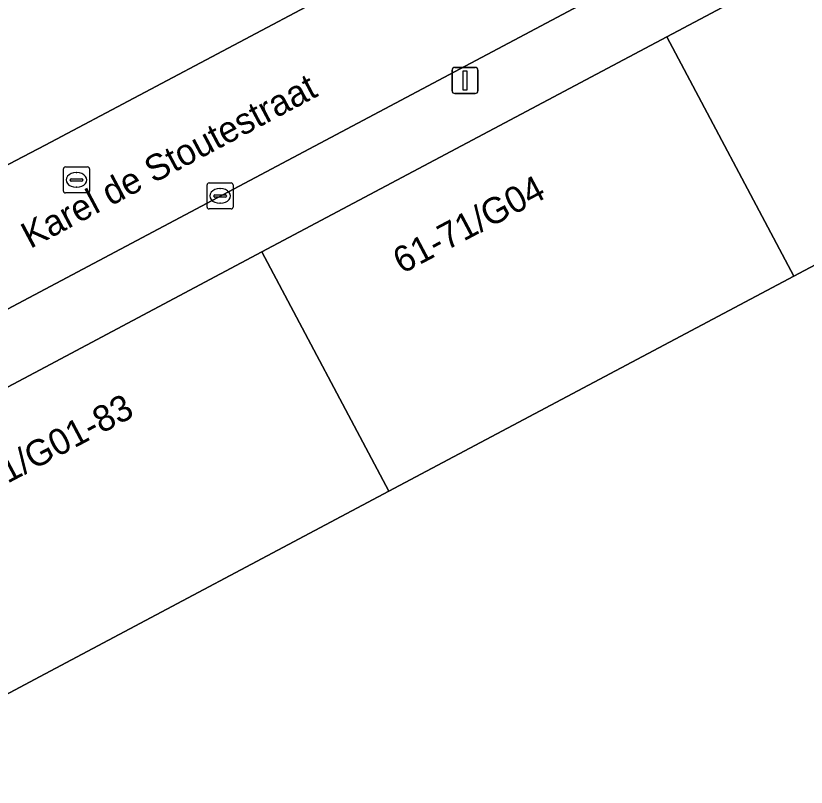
# Model space of a CAD drawing. Extents: x 159674 to 160531, y 382172 to 382904.
# Drawn here: x 159998.88 to 160029.22, y 382302.8 to 382332.4 of the extents above; entities that cross this region are included whole.
import ezdxf

# ---------------------------------------------------------------- set-up
doc = ezdxf.new("R2010")
doc.units = 0
for name, color, linetype in [('IMGEO_Groenvoorziening', 7, 'Continuous'), ('IMGEO_Kolk', 7, 'Continuous'), ('IMGEO_Lichtmast', 7, 'Continuous'), ('IMGEO_Openbare_ruimte_label', 7, 'Continuous'), ('IMGEO_Pand', 7, 'Continuous'), ('IMGEO_Pand_nummerreeks', 7, 'Continuous'), ('IMGEO_Parkeervlak_open', 7, 'Continuous'), ('IMGEO_Rijbaan_lokaal_open', 7, 'Continuous'), ('IMGEO_Rioolput', 7, 'Continuous'), ('IMGEO_Voetpad_open', 7, 'Continuous')]:
    doc.layers.add(name, color=color, linetype=linetype)

msp = doc.modelspace()

# ---------------------------------------------------------------- linework, layer by layer
at = {"layer": 'IMGEO_Groenvoorziening'}
for points in [[(160069.876, 382317.999), (160071.602, 382320.568), (160072.224, 382321.861), (160072.647, 382323.232), (160045.381, 382343.017), (160039.422, 382339.84), (160044.297, 382330.659), (160028.751, 382322.408), (160013.206, 382314.156), (160000, 382307.147), (159997.66, 382305.905), (159982.114, 382297.653), (159977.237, 382306.837), (159966.979, 382301.422), (160000, 382277.384), (160003.473, 382274.856), (160014.527, 382280.815), (160013.011, 382283.689), (160015.445, 382285.033)], [(159998.879, 382326.843), (160000, 382327.438), (160010.873, 382333.212), (160009.916, 382335.059), (160011.76, 382336.052), (160012.767, 382334.217), (160024.689, 382340.548)]]:
    msp.add_lwpolyline(points, dxfattribs=at)
at = {"layer": 'IMGEO_Kolk'}
for p, q in [((160006.222, 382325.062), (160006.222, 382325.914)), ((160006.297, 382325.988), (160007.149, 382325.988)), ((160007.223, 382325.914), (160007.223, 382325.062)), ((160006.524, 382325.531), (160006.922, 382325.531)), ((160006.71, 382325.768), (160006.735, 382325.768)), ((160006.481, 382325.482), (160006.481, 382325.494)), ((160006.919, 382325.445), (160006.521, 382325.445)), ((160006.965, 382325.494), (160006.965, 382325.482)), ((160007.149, 382324.988), (160006.297, 382324.988)), ((160006.733, 382325.208), (160006.708, 382325.208))]:
    msp.add_line(p, q, dxfattribs=at)
for points in [[(160006.222, 382325.062), (160006.222, 382325.914)], [(160006.297, 382325.988), (160007.149, 382325.988)], [(160007.223, 382325.914), (160007.223, 382325.062)], [(160007.149, 382324.988), (160006.297, 382324.988)]]:
    msp.add_lwpolyline(points, dxfattribs=at)
for centre, radius, start, end in [((160006.299, 382325.912), 0.0765, 91.552, 178.448), ((160006.299, 382325.912), 0.0765, 91.552, 178.448), ((160007.147, 382325.912), 0.0765, 1.552, 88.448), ((160007.147, 382325.912), 0.0765, 1.552, 88.448), ((160006.521, 382325.491), 0.0403, 85.8775, 175.7526), ((160006.926, 382325.493), 0.0386, 1.7309, 96.639), ((160006.518, 382325.481), 0.0366, 178.938, 274.7102), ((160006.922, 382325.488), 0.043, 264.8664, 352.4533), ((160006.299, 382325.064), 0.0765, 181.552, 268.448), ((160006.299, 382325.064), 0.0765, 181.552, 268.448), ((160007.147, 382325.064), 0.0765, 271.552, 358.448), ((160007.147, 382325.064), 0.0765, 271.552, 358.448)]:
    msp.add_arc(centre, radius, start, end, dxfattribs=at)
for centre, major_axis, ratio, start_param, end_param in [((160006.709, 382325.488), (-0.387, 0.002), 0.722429, 4.712389, 7.853982), ((160006.734, 382325.488), (-0.39, 0.002), 0.717154, 1.570796, 4.712389)]:
    msp.add_ellipse(centre, major_axis=major_axis, ratio=ratio, start_param=start_param, end_param=end_param, dxfattribs=at)
at = {"layer": 'IMGEO_Lichtmast'}
for p, q in [((160015.729, 382330.42), (160016.519, 382330.42)), ((160016.519, 382330.42), (160015.729, 382330.42)), ((160015.629, 382329.52), (160015.629, 382330.32)), ((160015.629, 382330.32), (160015.629, 382329.52)), ((160016.619, 382330.32), (160016.619, 382329.52)), ((160016.619, 382329.52), (160016.619, 382330.32)), ((160016.519, 382329.42), (160015.729, 382329.42)), ((160015.729, 382329.42), (160016.519, 382329.42))]:
    msp.add_line(p, q, dxfattribs=at)
msp.add_lwpolyline([(160016.049, 382330.295), (160016.199, 382330.295), (160016.199, 382329.545), (160016.049, 382329.545), (160016.049, 382330.295)], dxfattribs=at)
for centre, start, end in [((160015.729, 382330.32), 90, 180), ((160015.729, 382330.32), 90, 180), ((160016.519, 382330.32), 0, 90), ((160016.519, 382330.32), 360, 90), ((160015.729, 382329.52), 180, 270), ((160015.729, 382329.52), 180, 270), ((160016.519, 382329.52), 270, 0), ((160016.519, 382329.52), 270, 0)]:
    msp.add_arc(centre, 0.1, start, end, dxfattribs=at)
at = {"layer": 'IMGEO_Pand'}
for points in [[(160028.751, 382322.408), (160044.297, 382330.659), (160039.422, 382339.84), (160023.876, 382331.589)], [(160008.329, 382323.339), (160013.206, 382314.156), (160028.751, 382322.408), (160023.876, 382331.589)], [(159992.783, 382315.088), (159997.66, 382305.905), (160000, 382307.147), (160013.206, 382314.156), (160008.329, 382323.339), (160000, 382318.918)]]:
    msp.add_lwpolyline(points, close=True, dxfattribs=at)
at = {"layer": 'IMGEO_Parkeervlak_open'}
msp.add_lwpolyline([(159979.237, 382316.488), (159998.879, 382326.843)], dxfattribs=at)
at = {"layer": 'IMGEO_Rijbaan_lokaal_open'}
for points in [[(160024.689, 382340.548), (160012.767, 382334.217), (160010.873, 382333.212), (160000, 382327.438), (159998.879, 382326.843), (159979.237, 382316.488)], [(159977.738, 382314.014), (159977.115, 382313.657), (159975.28, 382312.603), (159974.461, 382312.133), (159975.985, 382309.171), (160000, 382321.916), (160022.355, 382333.786)]]:
    msp.add_lwpolyline(points, dxfattribs=at)
at = {"layer": 'IMGEO_Rioolput'}
for p, q in [((160000.708, 382325.676), (160000.708, 382326.528)), ((160000.783, 382326.602), (160001.635, 382326.602)), ((160001.709, 382326.528), (160001.709, 382325.676)), ((160001.01, 382326.145), (160001.408, 382326.145)), ((160001.196, 382326.382), (160001.221, 382326.382)), ((160000.967, 382326.096), (160000.967, 382326.108)), ((160001.405, 382326.059), (160001.007, 382326.059)), ((160001.451, 382326.108), (160001.451, 382326.096)), ((160001.635, 382325.602), (160000.783, 382325.602)), ((160001.219, 382325.822), (160001.194, 382325.822))]:
    msp.add_line(p, q, dxfattribs=at)
for points in [[(160000.708, 382325.676), (160000.708, 382326.528)], [(160000.783, 382326.602), (160001.635, 382326.602)], [(160001.709, 382326.528), (160001.709, 382325.676)], [(160001.635, 382325.602), (160000.783, 382325.602)]]:
    msp.add_lwpolyline(points, dxfattribs=at)
for centre, radius, start, end in [((160000.785, 382326.526), 0.0765, 91.552, 178.448), ((160000.785, 382326.526), 0.0765, 91.552, 178.448), ((160001.633, 382326.526), 0.0765, 1.552, 88.448), ((160001.633, 382326.526), 0.0765, 1.552, 88.448), ((160001.007, 382326.105), 0.0403, 85.8775, 175.7526), ((160001.412, 382326.107), 0.0386, 1.7309, 96.639), ((160001.004, 382326.095), 0.0366, 178.938, 274.7102), ((160001.408, 382326.102), 0.043, 264.8664, 352.4533), ((160000.785, 382325.678), 0.0765, 181.552, 268.448), ((160000.785, 382325.678), 0.0765, 181.552, 268.448), ((160001.633, 382325.678), 0.0765, 271.552, 358.448), ((160001.633, 382325.678), 0.0765, 271.552, 358.448)]:
    msp.add_arc(centre, radius, start, end, dxfattribs=at)
for centre, major_axis, ratio, start_param, end_param in [((160001.195, 382326.102), (-0.387, 0.002), 0.722429, 4.712389, 7.853982), ((160001.22, 382326.102), (-0.39, 0.002), 0.717154, 1.570796, 4.712389)]:
    msp.add_ellipse(centre, major_axis=major_axis, ratio=ratio, start_param=start_param, end_param=end_param, dxfattribs=at)
at = {"layer": 'IMGEO_Voetpad_open'}
msp.add_lwpolyline([(160022.355, 382333.786), (160000, 382321.916), (159975.985, 382309.171), (159964.599, 382303.191), (159966.979, 382301.422), (159977.237, 382306.837), (159992.783, 382315.088), (160000, 382318.918), (160008.329, 382323.339), (160023.876, 382331.589), (160039.422, 382339.84), (160045.381, 382343.017), (160040.366, 382346.657), (160040.837, 382345.739), (160039.322, 382344.96), (160038.558, 382346.447), (160039.785, 382347.078), (160038.644, 382347.906)], dxfattribs=at)

# ---------------------------------------------------------------- texts
at = {"layer": 'IMGEO_Openbare_ruimte_label'}
msp.add_text('Karel de Stoutestraat', height=1, rotation=27.9747, dxfattribs=at).set_placement((159999.434, 382323.449))
at = {"layer": 'IMGEO_Pand_nummerreeks'}
for s, rotation, p in [('61-71/G04', 27.9557, (160013.707, 382322.479)), ('71/G01-83', 27.956, (159997.902, 382314.091))]:
    msp.add_text(s, height=1, rotation=rotation, dxfattribs=at).set_placement(p)

doc.saveas('drawing.dxf')
